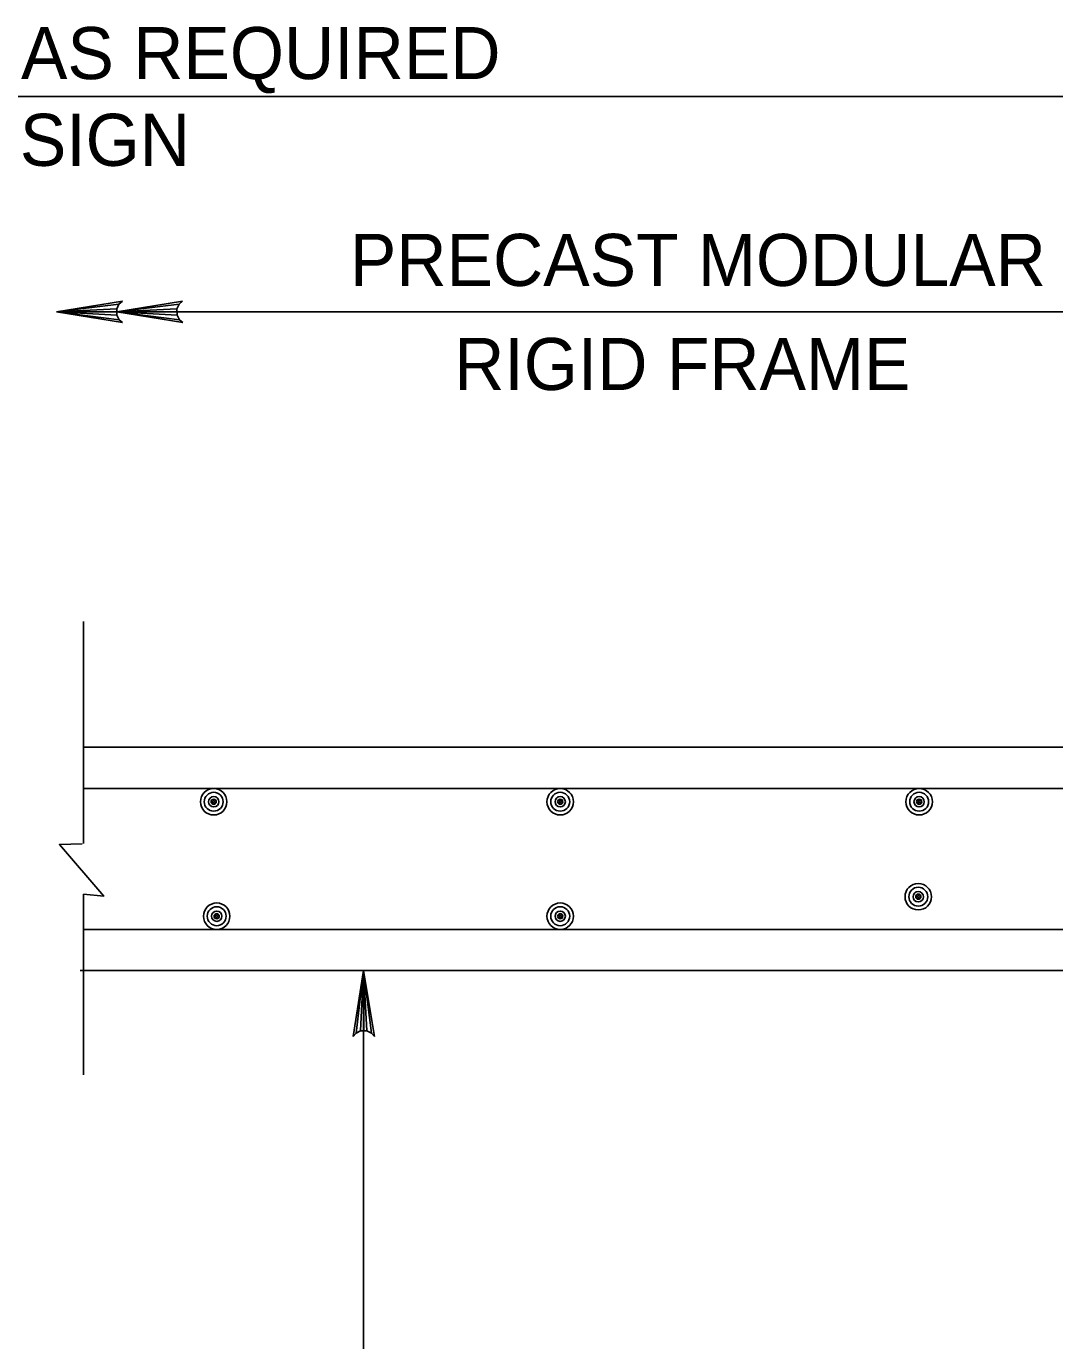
# Model space of a CAD drawing. Extents: x 641328 to 643024, y 298283 to 300065.
# Drawn here: x 641507.9 to 641567.2, y 299698.1 to 299773.9 of the extents above; entities that cross this region are included whole.
import ezdxf

# ---------------------------------------------------------------- set-up
doc = ezdxf.new("R2010")
doc.units = 0
doc.layers.add('2', color=7, linetype='Continuous')

msp = doc.modelspace()

# ---------------------------------------------------------------- linework, layer by layer
at = {"layer": '2'}
for p, q in [((641432.326, 299769.829), (641584.524, 299769.829)), ((641509.617, 299757.407), (641513.414, 299758.024)), ((641513.217, 299757.849), (641509.617, 299757.407)), ((641509.617, 299757.407), (641513.089, 299757.587)), ((641513.089, 299757.407), (641516.886, 299758.024)), ((641513.089, 299757.587), (641513.217, 299757.849)), ((641516.69, 299757.849), (641513.089, 299757.407)), ((641513.09, 299757.226), (641513.089, 299757.587)), ((641513.089, 299757.407), (641516.561, 299757.587)), ((641513.414, 299758.024), (641513.217, 299757.849)), ((641516.561, 299757.587), (641516.69, 299757.849)), ((641516.562, 299757.226), (641516.561, 299757.587)), ((641516.886, 299758.024), (641516.69, 299757.849)), ((641509.617, 299757.407), (641587.3, 299757.407)), ((641513.09, 299757.226), (641509.617, 299757.407)), ((641509.617, 299757.407), (641513.225, 299756.96)), ((641513.416, 299756.8), (641509.617, 299757.407)), ((641509.617, 299757.407), (641513.089, 299757.407)), ((641516.562, 299757.226), (641513.089, 299757.407)), ((641513.089, 299757.407), (641516.697, 299756.96)), ((641516.889, 299756.8), (641513.089, 299757.407)), ((641513.089, 299757.407), (641516.562, 299757.407)), ((641513.225, 299756.96), (641513.09, 299757.226)), ((641513.225, 299756.96), (641513.416, 299756.8)), ((641516.697, 299756.96), (641516.562, 299757.226)), ((641516.697, 299756.96), (641516.889, 299756.8)), ((641511.174, 299726.762), (641511.174, 299739.568)), ((641511.174, 299732.313), (641587.3, 299732.313)), ((641511.174, 299729.938), (641578.167, 299729.938)), ((641511.174, 299713.438), (641511.174, 299723.849)), ((641511.174, 299721.813), (641586.3, 299721.813)), ((641510.98, 299719.438), (641528.811, 299719.438)), ((641511.174, 299719.438), (641572.358, 299719.438)), ((641526.72, 299715.636), (641527.311, 299719.438)), ((641527.311, 299719.438), (641526.88, 299715.829)), ((641527.145, 299715.965), (641527.311, 299719.438)), ((641527.311, 299652.133), (641527.311, 299719.438)), ((641527.311, 299719.438), (641527.507, 299715.967)), ((641527.769, 299715.84), (641527.311, 299719.438)), ((641527.311, 299719.438), (641527.945, 299715.644)), ((641527.311, 299719.438), (641527.326, 299715.966)), ((641526.88, 299715.829), (641526.72, 299715.636)), ((641526.88, 299715.829), (641527.145, 299715.965)), ((641527.145, 299715.965), (641527.507, 299715.967)), ((641527.507, 299715.967), (641527.769, 299715.84)), ((641527.945, 299715.644), (641527.769, 299715.84))]:
    msp.add_line(p, q, dxfattribs=at)
msp.add_lwpolyline([(641511.174, 299723.849), (641512.336, 299723.731), (641509.785, 299726.704), (641511.096, 299726.748)], dxfattribs=at)
for centre, radius in [((641518.676, 299729.175), 0.763), ((641518.676, 299729.175), 0.545), ((641518.676, 299729.175), 0.298), ((641538.651, 299729.175), 0.763), ((641538.651, 299729.175), 0.545), ((641538.651, 299729.175), 0.298), ((641559.342, 299729.175), 0.763), ((641559.342, 299729.175), 0.545), ((641559.342, 299729.175), 0.298), ((641518.676, 299729.175), 0.15), ((641518.676, 299729.175), 0.0644), ((641538.651, 299729.175), 0.15), ((641538.651, 299729.175), 0.0644), ((641559.342, 299729.175), 0.15), ((641559.342, 299729.175), 0.0644), ((641559.292, 299723.701), 0.763), ((641559.292, 299723.701), 0.545), ((641559.292, 299723.701), 0.298), ((641559.292, 299723.701), 0.15), ((641559.292, 299723.701), 0.0644), ((641518.849, 299722.576), 0.763), ((641518.849, 299722.576), 0.545), ((641518.849, 299722.576), 0.298), ((641518.849, 299722.576), 0.15), ((641518.849, 299722.576), 0.0644), ((641538.651, 299722.576), 0.763), ((641538.651, 299722.576), 0.545), ((641538.651, 299722.576), 0.298), ((641538.651, 299722.576), 0.15), ((641538.651, 299722.576), 0.0644)]:
    msp.add_circle(centre, radius, dxfattribs=at)

# ---------------------------------------------------------------- texts
for s, height, p in [('REINFORCEMENT AS REQUIRED', 2.99999, (641471.464, 299770.829)), ('BY DESIGN', 3, (641495.464, 299765.829)), ('PRECAST MODULAR ', 2.99999, (641526.526, 299758.907)), ('RIGID FRAME', 2.99999, (641532.537, 299752.907))]:
    msp.add_text(s, height=height, dxfattribs=at).set_placement(p)

doc.saveas('drawing.dxf')
